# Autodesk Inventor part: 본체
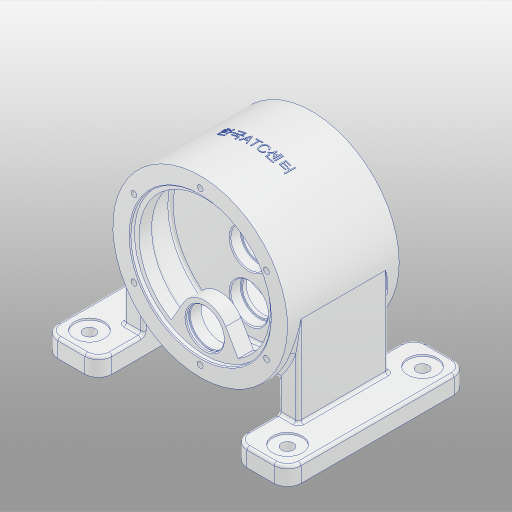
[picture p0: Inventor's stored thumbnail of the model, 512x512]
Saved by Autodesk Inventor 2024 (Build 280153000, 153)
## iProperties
Created: 2025-12
Part Number: 본체
Material: 알루미늄 6061
Document SubType Name: Modeling
Designer: Edu09
Density: 2.7 g/cm^3
Appearance: 알루미늄 - 평지
Mass: 5626.86 g
Surface Area: 3057.74 cm^2
Volume: 2084.02 cm^3
Author: Edu09
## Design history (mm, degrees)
sketch "스케치1"
  geometry: C1 r 97 at (0, 0); 1 further point
  constraints: 1 centre point, 1 coincident
  dimensions: "d0" = 194 diameter of C1
extrude "돌출1" new body sketch "스케치1" stored distance "d1" = 124; taper "d2" = 0 deg
node "작업 평면1"
sketch "스케치2"
  geometry: L1 (135, 100)-(-135, 100); L2 (-135, 100)-(-135, -100); L3 (-135, -100)-(135, -100); L4 (135, -100)-(135, 100); L5 (135, 100)-(-135, -100); L6 (-135, 100)-(135, -100); 1 further point
  constraints: 12 end point, 2 midpoint, 2 parallel, 1 horizontal, 1 perpendicular
  dimensions: "d4" = 200 distance of L1.end L2.end; "d5" = 270 distance of L1.start L1.end
extrude "돌출2" join sketch "스케치2" distance "d6" = 20; taper "d7" = 0 deg
sketch "스케치3"
  geometry: L1 (135, -100)-(135, 100) reference; L2 (-135, 100)-(-135, -100) reference; L3 (-97, -50)-(97, -50); L4 (97, -50)-(97, 50); L5 (97, 50)-(-97, 50); L6 (-97, 50)-(-97, -50); L7 (-97, -50)-(97, 50); L8 (97, -50)-(-97, 50); 1 further point
  constraints: 12 end point, 2 midpoint, 2 parallel, 1 horizontal, 1 perpendicular
  dimensions: "d8" = 38 distance between parallel lines of L1 L4; "d9" = 38 distance between parallel lines of L2 L6 (derived); "d10" = 100 distance of L3.end L4.end
extrude "돌출3" join sketch "스케치3" stored distance "d11" = 20; taper "d12" = 0 deg
sketch "스케치4"
  geometry: L1 (0, 0)-(270, 0) reference; L2 (38, 20)-(38, 120) reference; L3 (232, 20)-(38, 20) reference; L4 (232, 20)-(232, 120) reference; L5 (60, 0)-(60, 58.486); L6 (210, 0)-(210, 58.486); C1 r 97 at (135, 120) reference; A1 r 97 centre (135, 120) between (38, 120) and (232, 120) reference; 3 further points
  constraints: 4 end point, 2 point on circle, 2 point on line, 2 vertical, 1 parallel
  dimensions: "d13" = 150 distance between parallel lines of L5 L6
extrude "돌출4" cut sketch "스케치4" extent not by distance; stored distance "d14" = 0; taper "d15" = 0 deg
sketch "스케치5"
  geometry: L1 (-97, -100)-(-75, -100) reference; L2 (-75, -61.514)-(-75, -100) reference; L3 (75, -100)-(75, -61.514) reference; L4 (-36.6, -89.83)-(-75, -112); L5 (-75, -120)-(-135, -120) reference; L6 (-75, -100)-(-75, -120) reference; A1 r 97 centre (0, 0) between (-75, -61.514) and (75, -61.514) reference; 1 further point
  constraints: 2 end point, 1 point on circle, 1 point on line
  dimensions: "d16" = 60 deg angle of L2 L4; "d17" = 8 distance from line of L4.end L5
extrude "돌출5" join sketch "스케치5" stored distance "d18" = 12; taper "d19" = 0 deg
fillet "모깎기1" dims "d20" = 15
sketch "스케치6"
  geometry: L1 (75, 85)-(75, 50) reference; L2 (75, 50)-(97, 50) reference; L3 (97, 50)-(97, -50) reference; L4 (97, -50)-(75, -50) reference; L5 (75, -50)-(75, -85) reference; L6 (90, -100)-(120, -100) reference; L7 (135, -85)-(135, 85) reference; L8 (120, 100)-(90, 100) reference; L9 (-110, -75)-(110, -75); L10 (110, -75)-(110, 75); L11 (110, 75)-(-110, 75); L12 (-110, 75)-(-110, -75); L13 (-110, -75)-(110, 75); L14 (110, -75)-(-110, 75); A1 r 15 centre (90, 85) between (90, 100) and (75, 85) reference; A2 r 15 centre (90, -85) between (75, -85) and (90, -100) reference; A3 r 15 centre (120, -85) between (120, -100) and (135, -85) reference; A4 r 15 centre (120, 85) between (135, 85) and (120, 100) reference; 1 further point
  constraints: 12 end point, 2 midpoint, 2 parallel, 1 horizontal, 1 perpendicular
  dimensions: "d21" = 150 distance of L9.end L10.end; "d22" = 220 distance of L10.end L11.end
hole "구멍1" sketch "스케치6" at (-110, 75), (-110, -75), (110, -75), (110, 75) diameter "d23" = 13.5; stored, may be unused: countersink angle "d27" = 90 deg, drill point angle "d29" = 118 deg; dims "d24" = 6, "d25" = 33, "d26" = 2, "d28" = 8
sketch "스케치7"
  geometry: L1 (97, 62)-(-97, 62) reference; L2 (-97, -62)-(97, -62) reference; L3 (0, 62)-(0, -62); L4 (78, -62)-(78, -57); L5 (78, -57)-(73, -57); L6 (73, -57)-(73, -40); L7 (73, -40)-(87, -40); L8 (87, -40)-(87, -8); L9 (87, -8)-(0, -8); 1 further point
  constraints: 14 end point, 5 perpendicular, 2 midpoint, 2 point on line, 1 vertical
  dimensions: "d30" = 174 diameter of L8 L3; "d31" = 156 diameter of L4 L3; "d32" = 146 diameter of L6 L3; "d33" = 32 distance of L7.end L8.end; "d34" = 22 distance between parallel lines of L2 L7; "d35" = 5 distance of L4.start L4.end
revolve "회전1" sketch "스케치7" stored, may be unused: angle "d36" = 90 deg
sketch "스케치9"
  geometry: L1 (97, 62)-(-97, 62) reference; L2 (78, -62)-(-78, -62) reference; L3 (0, 62)-(0, -62); L4 (87, -8)-(-87, -8) reference; L5 (19, -8)-(19, -4); L6 (19, -4)-(21, -4); L7 (21, -4)-(21, 8); L8 (21, 8)-(0, 8); 2 further points
  constraints: 10 end point, 3 perpendicular, 2 midpoint, 2 point on line, 1 vertical
  dimensions: "d37" = 42 diameter of L7 L3; "d38" = 38 diameter of L5 L3; "d39" = 66 distance between parallel lines of L1 L6; "d40" = 54 distance between parallel lines of L1 L8
revolve "회전2" sketch "스케치9" stored, may be unused: angle "d41" = 90 deg
sketch "스케치10"
  geometry: L1 (97, 62)-(-97, 62) reference; L2 (78, -62)-(-78, -62) reference; L3 (-52.5, 62)-(-52.5, -62); L4 (87, -8)-(-87, -8) reference; L5 (-33.5, -8)-(-33.5, -4); L6 (-33.5, -4)-(-31.5, -4); L7 (-31.5, -4)-(-31.5, 8); L8 (-31.5, 8)-(-52.5, 8); L9 (21, 8)-(-21, 8) reference; L10 (19, -4)-(-19, -4) reference; 2 further points
  constraints: 10 end point, 4 perpendicular, 4 point on line, 2 collinear, 1 vertical
  dimensions: "d42" = 52.5 horizontal distance of L3.start point (0, 0); "d43" = 42 diameter of L7 L3; "d44" = 38 diameter of L5 L3
revolve "회전3" sketch "스케치10" stored, may be unused: angle "d45" = 90 deg
sketch "스케치11"
  geometry: L1 (97, 62)-(-97, 62) reference; L2 (78, -62)-(-78, -62) reference; L3 (0, 62)-(0, -62); L4 (21, 8)-(-21, 8) reference; L5 (0, 8)-(87, 8); L6 (87, 8)-(87, 40); L7 (87, 40)-(0, 40); 3 further points
  constraints: 8 end point, 3 midpoint, 2 perpendicular, 1 horizontal, 1 point on line
  dimensions: "d46" = 32 distance of L5.end L6.end; "d47" = 22 distance between parallel lines of L1 L7 (derived); "d48" = 174 diameter of L6 L3
revolve "회전4" sketch "스케치11" stored, may be unused: angle "d49" = 90 deg
sketch "스케치12"
  geometry: L1 (97, 62)-(-97, 62) reference; L2 (0, 62)-(0, -62); L3 (78, -62)-(-78, -62) reference; L4 (0, 57)-(78, 57); L5 (78, 57)-(78, 62); 1 further point
  constraints: 6 end point, 2 midpoint, 2 point on line, 1 horizontal, 1 perpendicular
  dimensions: "d50" = 156 diameter of L5 L2; "d51" = 5 distance of L4.end L5.end
revolve "회전5" sketch "스케치12" stored, may be unused: angle "d52" = 90 deg
sketch "스케치13"
  geometry: L1 (-23.383, -39)-(-37.148, -62.842); L2 (23.383, -39)-(37.148, -62.842); L3 (0, 0)-(0, -97); C1 r 78 at (0, 0) reference; A1 r 73 centre (0, 0) between (-37.148, -62.842) and (37.148, -62.842); A2 r 27 centre (0, -52.5) between (-23.383, -39) and (23.383, -39); 1 further point
  constraints: 6 end point, 4 point on circle, 2 centre point, 2 tangent, 2 vertical alignment, 1 coincident, 1 vertical, 1 other
  dimensions: "d53" = 146 diameter of A1; "d54" = 30 deg angle of L3 L2; "d55" = 30 deg angle of L3 L1; "d56" = 54 diameter of A2; "d57" = 52.5 distance of A2.centre C1.centre
extrude "돌출6" cut sketch "스케치13" stored distance "d58" = 12; taper "d59" = 0 deg
sketch "스케치14"
  geometry: L1 (-78, 62)-(78, 62) reference; L2 (78, -62)-(-78, -62) reference; L3 (-52.5, 62)-(-52.5, -62); L4 (-62.842, 57)-(73, 57) reference; L5 (-31.5, 57)-(-31.5, 53.95); L6 (-31.5, 53.95)-(-30.25, 53.95); L7 (-30.25, 53.95)-(-30.25, 52); L8 (-30.25, 52)-(-31.5, 52); L9 (-31.5, 52)-(-31.5, 40); L10 (-39, 40)-(-25.5, 40) reference; L11 (-62.842, 40)-(-39, 40) reference; 3 further points
  constraints: 12 end point, 4 point on line, 3 perpendicular, 1 horizontal, 1 vertical
  dimensions: "d60" = 52.5 distance from line of L3 point (0, 0); "d61" = 44.5 diameter of L7 L3; "d62" = 42 diameter of L5 L3; "d63" = 42 diameter of L9 L3; "d64" = 12 distance between parallel lines of L8 L11; "d65" = 1.95 distance of L6.end L7.end
revolve "회전6" sketch "스케치14" stored, may be unused: angle "d66" = 90 deg
fillet "모깎기2" dims "d67" = 0.6
chamfer "모따기1" distance "d68" = 1; stored, may be unused: second distance "d69" = 2, angle "d70" = 45 deg
fillet "모깎기3" dims "d71" = 3
fillet "모깎기4" dims "d72" = 3
fillet "모깎기5" dims "d73" = 3
fillet "모깎기7" dims "d75" = 3
fillet "모깎기8" dims "d76" = 3
fillet "모깎기9" dims "d77" = 3
fillet "모깎기10" dims "d78" = 3
fillet "모깎기11" dims "d79" = 3
fillet "모깎기12" dims "d80" = 3
fillet "모깎기13" dims "d81" = 3
fillet "모깎기14" dims "d82" = 3
fillet "모깎기15" dims "d83" = 3
fillet "모깎기16" dims "d84" = 3
sketch "스케치15"
  geometry: L1 (0, 0)-(0, 85); C1 r 79 at (0, 0) reference
  constraints: 2 end point, 1 vertical
  dimensions: "d85" = 85 distance of L1.start L1.end
hole "구멍2" sketch "스케치15" at (0, 85) diameter "d86" = 6.647; stored, may be unused: countersink angle "d90" = 90 deg, drill point angle "d92" = 118 deg; dims "d87" = 16, "d88" = 4, "d89" = 2, "d91" = 18
sketch "스케치16"
  geometry: 2 further points
  constraints: 1 coincident, 1 other
feature "엠보싱1" sketch "스케치16" dims "d8" = 38, "d9" = 38 (derived), "d10" = 100, "d96" = 0.5, "d97" = 0
node "솔리드1"
mirror "미러1"
pattern_circular "원형 패턴1" dims angle "d94" = 360 deg
mirror "미러2"
node "투영된 루프1"
node "투영된 루프2"
node "투영된 루프3"
node "투영된 루프4"
feature "A9D066F2-1C7D-4E18-AEED-F7BC21143FA4" dims "d86" = 6.647, "d87" = 16, "d88" = 4, "d89" = 2, "d90" = 90 deg, "d91" = 18, "d92" = 118 deg
